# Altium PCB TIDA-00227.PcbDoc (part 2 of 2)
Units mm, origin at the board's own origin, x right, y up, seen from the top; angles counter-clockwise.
Board outline 100 x 100 mm, 2 copper layers (Top Layer, Bottom Layer), stack 1.575 mm thick; 148 components, 67 nets, 312 pads, 76 vias.
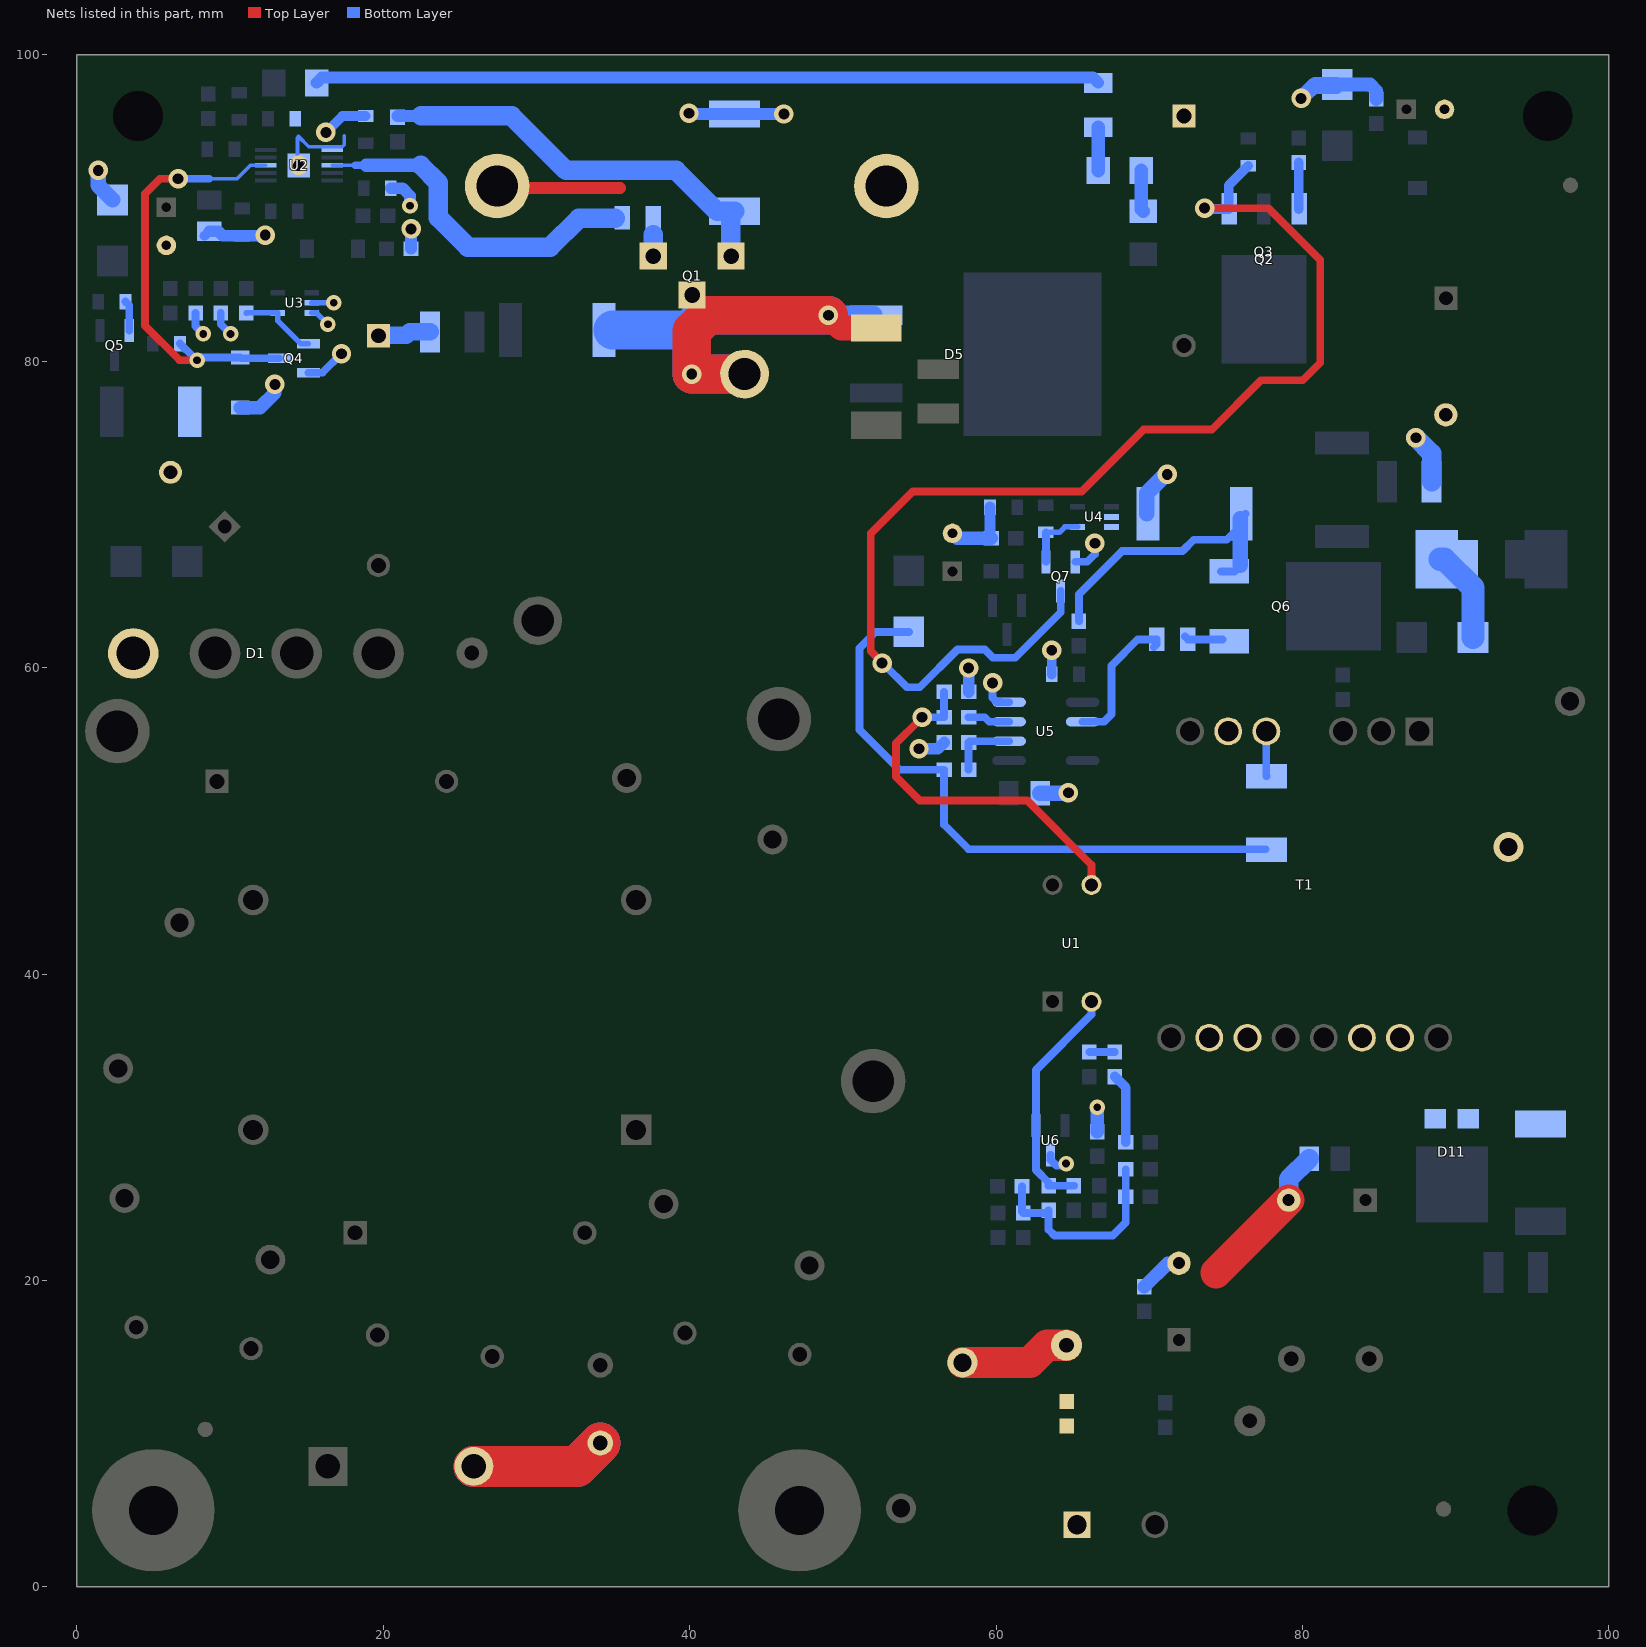
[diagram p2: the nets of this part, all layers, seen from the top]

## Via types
v1: diameter 1.27, hole 0.711, Top Layer to Bottom Layer, tented both sides, 65 vias
v2: diameter 1.016, hole 0.508, Top Layer to Bottom Layer, tented both sides, 8 vias
v3: diameter 2, hole 1, Top Layer to Bottom Layer, tented both sides, 3 vias

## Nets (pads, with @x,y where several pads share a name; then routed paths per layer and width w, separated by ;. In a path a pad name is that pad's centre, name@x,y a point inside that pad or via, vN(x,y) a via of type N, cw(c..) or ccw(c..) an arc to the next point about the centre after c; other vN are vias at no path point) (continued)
NetD5_3: D5.3 L1.2 Q1.2 R1.1 R19.2 | length 43
  Top Layer w1.651: v1(49.047,83.007) 49.886,82.169 R1.1@52.172,82.169
  Top Layer w2.54: L1.2@43.579,79.163 v1(40.132,79.163) 40.132,81.966 41.173,83.007 v1(49.047,83.007)
  Bottom Layer w1.245: v1(49.047,83.007) D5.3@51.967,83.007
  Bottom Layer w2.54: R19.2@34.976,82.042 39.929,82.042 40.132,82.245 ; L1.2@43.579,79.163 v1(40.132,79.163) 40.132,82.245 ; v1(49.047,83.007) 40.894,83.007 40.132,82.245
NetD7_1: D7.1 D9.1 D14.1 | length 6.1
  Bottom Layer w1.524: D7.1@88.989,67.081 89.256,67.081 91.129,65.208 D9.1@91.129,61.976
NetD8_2: D8.2 R32.1 R33.2 | length 40.8
  Bottom Layer w0.508: D8.2@54.305,62.338 52.153,62.338 51.079,61.265 51.079,55.956 53.696,53.34 R33.2@56.604,53.34 56.604,49.746 58.204,48.146 R32.1@77.597,48.146
NetD11_1: D11.1 D11.2 R36.1 T1.12 T1.13
NetD12_1: D12.1 Q4.3 R21.2 U2.3 | length 28.3
  Top Layer w0.508: v1(6.604,91.913) 5.426,91.913 4.445,90.932 4.445,82.321 6.706,80.061 v2(7.849,80.061)
  Bottom Layer w0.254: 8.636,91.913 10.455,91.913 11.339,92.796 U2.3@12.331,92.796
  Bottom Layer w0.508: v1(6.604,91.913) 8.636,91.913 ; R21.2@6.731,81.153 v2@7.62,80.264 ; v2(7.849,80.061) 8.038,80.25 D12.1@10.668,80.25 10.721,80.198 Q4.3@13.213,80.198
NetF1_1: F1.1 J1.2 | length 17.8
  Top Layer w2.667: J1.2@25.908,7.874 32.639,7.874 F1.1@34.163,9.398
  Bottom Layer w2.667: J1.2@25.908,7.874 32.639,7.874 F1.1@34.163,9.398
NetQ1_1: Q1.1 R14.2 | length 1.4
  Bottom Layer w1.27: Q1.1@37.617,86.868 37.617,88.265
NetQ1_3: Q1.3 R5.1 R6.2 | length 27.6
  Bottom Layer w0.762: R6.2@20.93,96.012 22.479,96.012
  Bottom Layer w0.889: R5.1@42.672,89.535 R5.1@42.926,89.789
  Bottom Layer w1.27: 22.479,96.012 28.372,96.012 31.928,92.456 39.116,92.456 41.783,89.789 R5.1@42.926,89.789 ; Q1.3@42.672,86.868 R5.1@42.672,89.535
NetQ2_1: Q2.1 Q3.1 Q7.3 R9.1 | length 79.5
  Top Layer w0.508: v1(52.553,60.3) 52.603,60.3 51.816,61.087 51.816,68.758 54.559,71.501 65.583,71.501 69.621,75.54 74.066,75.54 77.292,78.765 80.01,78.765 81.153,79.908 81.153,86.614 77.775,89.992 v1(73.609,89.992)
  Bottom Layer w0.508: v1(52.553,60.3) 52.603,60.3 54.178,58.725 55.016,58.725 57.48,61.189 59.258,61.189 59.792,60.655 61.239,60.655 64.211,63.627 Q7.3@64.211,65.014
  Bottom Layer w0.635: v1(73.609,89.992) 73.657,89.945 75.185,89.945 75.185,91.492 R9.1@76.454,92.761
NetQ2_3: Q2.3 Q3.3 R8.2 | length 3
  Bottom Layer w0.635: Q3.3@79.755,89.945 R8.2@79.756,92.977 R8.2@79.756,92.977
NetQ4_1: Q4.1 R16.2 U3.4 | length 5.2
  Bottom Layer w0.356: R16.2@11.049,83.147 11.059,83.157 U3.4@13.117,83.157 13.117,82.641 14.61,81.148 Q4.1@15.113,81.148
NetQ5_2: Q5.2 R20.1 | length 2
  Bottom Layer w0.508: R20.1@3.175,83.896 3.414,83.657 Q5.2@3.414,82.001
NetQ6_1: Q6.1 R28.2 | length 2.5
  Bottom Layer w0.508: R28.2@72.324,62.042 R28.2@72.517,61.849 74.33,61.849 Q6.1@74.778,61.849
NetQ6_3: Q6.3 R23.1 R27.2 | length 19.6
  Bottom Layer w0.508: R27.2@65.405,63.03 65.405,64.795 68.224,67.615 72.161,67.615 72.896,68.349 75.055,68.349 75.946,69.24 R23.1@75.946,69.721 ; Q6.3@74.682,66.288 Q6.3@75.213,66.288 75.559,66.288 Q6.3@75.946,66.675 ; R23.1@75.997,69.772 R23.1@75.946,69.721 ; R23.1@76.278,70.053 R23.1@75.946,69.721
  Bottom Layer w1.016: Q6.3@75.946,66.675 R23.1@75.946,69.721
NetQ7_1: Q7.1 R24.2 U4.4 | length 4.1
  Bottom Layer w0.356: R24.2@63.246,68.834 64.135,68.834 64.488,69.187 U4.4@65.314,69.187
  Bottom Layer w0.508: R24.2@63.246,68.834 63.246,66.929 Q7.1@63.261,66.914
NetR2_1: R2.1 R3.1 | length 51.3
  Bottom Layer w0.762: R3.1@15.646,98.171 16.002,98.527 66.322,98.527 R2.1@66.675,98.173
NetR2_2: R2.2 R10.2 | length 2.8
  Bottom Layer w0.889: R10.2@66.675,92.456 R2.2@66.675,95.273
NetR10_1: R10.1 R11.2 | length 2.7
  Bottom Layer w0.889: R10.1@69.469,92.456 69.469,89.916 R11.2@69.596,89.789
NetR14_1: R14.1 U2.8 | length 23.6
  Bottom Layer w0.254: U2.8@16.675,92.796 18.186,92.796
  Bottom Layer w0.508: 18.186,92.796 18.887,92.796
  Bottom Layer w0.889: 18.887,92.796 22.443,92.796 ; 22.215,92.796 22.817,92.194
  Bottom Layer w1.27: 22.443,92.796 23.597,91.643 23.597,89.383 25.527,87.452 30.886,87.452 32.766,89.332 R14.1@35.154,89.332
NetR28_1: R28.1 U5.6 | length 9.5
  Bottom Layer w0.508: U5.6@65.646,56.475 67.041,56.475 67.526,56.96 67.526,60.135 69.24,61.849 R28.1@70.485,61.849 70.485,61.544 R28.1@70.282,61.341
NetR29_2: R29.2 R30.1 U1.3 | length 24
  Top Layer w0.508: v1@55.169,56.54 54.94,56.54 53.467,55.067 53.467,52.883 55.016,51.333 62.027,51.333 66.218,47.142 U1.3@66.218,45.822
  Bottom Layer w0.508: v1(55.169,56.769) R30.1@56.604,56.769 R29.2@56.604,58.42
NetR30_2: R30.2 U5.3 | length 2.8
  Bottom Layer w0.508: R30.2@58.204,56.769 59.258,56.769 59.552,56.475 U5.3@60.846,56.475
NetR31_2: R31.2 R33.1 U5.2 | length 4.5
  Bottom Layer w0.508: R33.1@58.204,53.34 R31.2@58.204,55.118 58.291,55.205 U5.2@60.846,55.205
NetR32_2: R32.2 T1.4 | length 2.9
  Bottom Layer w0.508: T1.4@77.637,55.847 77.637,52.931 R32.2@77.648,52.921
NetR34_1: R34.1 R35.2 | length 1.7
  Bottom Layer w0.508: R35.2@66.091,34.912 R34.1@67.742,34.912
NetR34_2: R34.2 R38.1 | length 4.6
  Bottom Layer w0.635: R34.2@67.742,33.312 68.466,32.588 R38.1@68.466,29.032
NetR39_1: R39.1 R41.2 R42.2 R43.1 R44.1 | length 13.8
  Bottom Layer w0.508: R42.2@61.684,26.149 61.684,24.498 R44.1@61.773,24.409 63.246,24.409 R41.2@63.424,24.587 63.424,23.317 63.805,22.936 67.615,22.936 68.466,23.787 R43.1@68.466,25.476 R39.1@68.466,27.254
NetR40_1: R40.1 R41.1 U1.2 U6.1 | length 15.5
  Bottom Layer w0.508: R40.1@65.075,26.187 R41.1@63.424,26.187 63.424,26.391 62.601,27.214 U6.1@62.601,30.109 62.601,33.746 66.218,37.363 U1.2@66.218,38.202
PGND: C1.2 C2.1 C3.2 C4.1 C6.2 C7.2 C18.2 C20.1 C22.1 C23.2 C24.1 C25.2 C26.2 C27.1 C28.2 C29.2 C30.1 C31.1 C37.2 D1.4 D2.2 D4.2 D12.2 HT1.1 HT1.2 Q4.2 Q7.2 R5.2 R7.2 R15.1 R17.2 R23.2 R25.2 R29.1 R31.1 T1.5 U2.6 U2.11 U3.2 U3.3 U4.2 U4.3 U5.4 | length 78.6
  Top Layer w0.762: HT1.2@27.432,90.83 27.432,91.313 35.458,91.313
  Bottom Layer w0.254: v1(14.478,92.786) 14.402,92.862 14.402,94.59 14.478,94.666 15.138,94.005 17.323,94.005 17.45,94.132 17.45,94.717
  Bottom Layer w0.356: U3.3@15.326,83.157 15.649,83.157 v2(16.383,82.423) ; U3.2@15.326,83.817 16.761,83.817 v2(16.764,83.82)
  Bottom Layer w0.508: R17.2@7.747,83.147 7.747,82.296 v2(8.255,81.788) ; C25.2@9.398,83.147 9.398,82.423 v2(10.033,81.788) ; Q4.2@15.113,79.248 16.027,79.248 v1(17.272,80.493) ; v1(59.766,59.004) 59.766,58.039 60.046,57.76 60.35,57.76 60.365,57.745 U5.4@60.846,57.745 ; Q7.2@65.161,66.914 65.949,66.914 66.446,67.412 v1(66.446,68.123)
  Bottom Layer w0.635: C23.2@8.331,88.189 C23.2@8.56,88.417 ; v1(16.256,94.945) 17.323,96.012 C20.1@18.847,96.012 ; C30.1@63.627,59.563 v1(63.627,61.138) ; 80.518,97.765 D2.2@82.271,97.765
  Bottom Layer w0.737: R25.2@59.601,70.485 59.601,68.542 C29.2@59.69,68.453
  Bottom Layer w0.762: C23.2@8.636,88.494 9.22,88.494 9.525,88.189 C24.1@10.795,88.189 12.243,88.189 v1(12.294,88.24) ; C22.1@20.498,91.288 21.26,91.288 21.742,90.805 v2(21.742,90.145) ; R15.1@21.806,87.351 21.806,88.633 v1(21.819,88.646) ; v1@39.954,96.139 R5.2@42.926,96.139 v1(46.152,96.139) ; v1(54.966,54.712) 56.198,54.712 R31.1@56.604,55.118 ; R29.1@58.204,58.42 v1(58.204,59.982)
  Bottom Layer w0.889: D12.2@10.668,76.976 11.952,76.976 12.929,77.953 v1(12.929,78.486) ; C7.2@57.15,68.77 57.468,68.453 C29.2@59.69,68.453 ; D2.2@82.271,98.063 84.411,98.063 84.811,97.663 C18.2@84.811,97.117
  Bottom Layer w1.016: v1(1.397,92.456) 1.397,91.478 D4.2@2.337,90.538 ; C31.1@62.865,51.816 64.745,51.816 v1(64.719,51.841) ; R23.2@69.823,70.053 69.823,70.409 69.832,70.399 69.832,71.382 v1@71.171,72.72 ; v1(79.908,97.155) 80.518,97.765 80.816,98.063 D2.2@82.271,98.063
  Bottom Layer w1.143: C4.1@20.066,81.686 21.488,81.686 21.717,81.915 C26.2@23.061,81.915
  Bottom Layer w1.27: v1(87.401,75.006) 88.42,73.988 C28.2@88.42,72.136
  other v1: 71.171,72.619 39.954,96.19
PWR_GND: B1.2 J2.1
PWRGND: B1.1 C8.2 C12.2 C16.2 C17.2 C32.2 C36.2 R37.1 T1.8 T1.9 TP3.1 U6.3 | length 23.3
  Top Layer w2.032: C17.2@57.81,14.643 62.192,14.643 63.322,15.773 TP3.1@64.592,15.773 ; 74.358,20.511 C12.2@79.096,25.248
  Bottom Layer w0.508: U6.3@63.551,28.209 63.551,27.889 63.932,27.508 64.44,27.508 v2(64.567,27.635)
  Bottom Layer w0.889: R37.1@66.599,29.705 v2(66.599,31.318) ; C36.2@69.672,19.596 71.209,21.133 C16.2@71.933,21.133
  Bottom Layer w1.27: C12.2@79.096,25.248 79.096,26.619 C32.2@80.442,27.965
pads on no net: D5.1 D10.2 FID1.1 FID2.1 FID3.1 FID4.1 FID5.1 FID6.1 H1.1 H2.1 H3.1 H4.1 H5.1 H8.1 LBL1.0 Q3.2 T1.2 T1.6 T1.7 T1.10 T1.11 T1.14 U3.1 U4.1

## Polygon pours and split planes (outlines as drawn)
EARTH on Bottom Layer "Bottom Layer-No Net" (solid, pour order 50): 1.905,3.81 3.683,2.007 4.699,2.007 5.232,2.54 5.207,3.937 5.207,26.543 4.318,27.432 4.318,31.877 3.81,32.385 3.81,34.544 3.429,34.925 2.032,34.925 1.651,34.544 1.651,32.512 1.905,32.258
EARTH on Bottom Layer "Bottom Layer-No Net" (solid, remove dead copper, pour order 54): 44.323,46.863 45.847,45.339 45.847,28.321 46.482,27.686 46.482,7.62 45.466,6.604 45.466,3.556 46.482,2.54 48.133,2.54 49.784,4.191 49.784,28.448 49.149,29.083 49.149,44.831 46.482,47.498 46.482,49.53 46.101,49.911 44.45,49.911 44.323,49.784
NetC13_1 on Bottom Layer "Bottom Layer-No Net" (solid, remove dead copper, pour order 41): 16.256,24.384 16.256,20.066 20.447,20.066 20.828,20.447 20.828,23.749 19.939,24.638 16.51,24.638
PGND on Bottom Layer "Top Layer-No Net 1" (hatched 90Degree grid 0.127 track 0.254, remove dead copper, pour order 43): 5.588,72.136 5.334,72.39 5.334,73.152 6.477,74.295 6.477,78.486 6.731,78.74 8.763,78.74 9.779,77.724 12.446,77.724 12.446,76.962 12.192,76.708 10.668,76.708 7.239,73.279 7.239,72.39 6.985,72.136
NetC4_2 on Bottom Layer "Bottom Layer-No Net" (solid, pour order 42): 18.034,67.564 17.399,68.199 9.525,68.199 9.525,70.358 10.541,71.374 19.05,71.374 21.361,69.063 21.361,60.198 20.396,59.233 18.974,59.233 18.034,60.173
NetD5_3 on Bottom Layer "Bottom Layer-No Net" (solid, pour order 65): 40.97,84.785 39.802,84.785 38.1,83.083 38.1,81.153 39.611,79.642 42.062,82.093 42.062,83.693
PWRGND on Bottom Layer "Bottom Layer-No Net" (solid, pour order 63): 79.477,28.778 78.054,27.356 78.054,24.587 78.359,24.282 79.629,24.282 79.959,24.613 79.959,26.391 80.67,27.102 81.077,27.102 81.077,28.727 81.026,28.778
PWRGND on Bottom Layer "Bottom Layer-No Net" (solid, pour order 62): 70.028,21.946 68.859,20.777 68.859,19.329 69.088,19.101 70.282,19.101 70.282,19.736 70.815,20.269 72.238,20.269 72.72,20.752 72.72,21.539 72.314,21.946
NetB3_1 on Bottom Layer "Bottom Layer-No Net" (solid, pour order 59): 70.206,11.608 69.164,12.649 69.164,18.491 70.231,18.491 70.688,18.034 70.688,17.17 70.968,16.891 78.613,16.891 80.188,15.316 80.188,12.243 77.699,9.754 75.26,9.754 73.406,11.608
15V on Bottom Layer "Bottom Layer-No Net" (solid, pour order 60): 71.298,10.77 70.333,10.77 70.231,10.668 69.469,9.906 69.469,3.632 69.952,3.15 71.603,3.15 72.847,4.394 72.847,9.5 71.679,10.668 71.577,10.77 71.222,10.77
NetC35_1 on Bottom Layer "Bottom Layer-No Net" (solid, pour order 57): 96.774,24.765 94.183,24.765 93.929,24.511 93.904,24.486 93.904,23.266 93.904,23.012 94.666,22.25 94.717,22.2 94.717,21.082 94.717,19.253 94.767,19.202 95.885,19.202 96.444,19.202 96.977,19.736 97.206,19.964 97.206,23.139 97.206,24.765 97.079,24.765
NetC12_1 on Bottom Layer "Bottom Layer-No Net" (solid, pour order 56): 85.065,28.245 84.074,29.235 82.296,29.235 81.864,28.804 81.864,27.153 83.312,25.705 83.312,14.529 83.998,13.843 86.335,13.843 90.881,18.39 92.735,18.39 93.193,18.847 93.193,21.895 92.075,23.012 92.075,27.254 91.084,28.245
NetD11_1 on Bottom Layer "Bottom Layer-No Net" (solid, pour order 55): 83.693,36.805 86.741,36.805 87.147,36.398 87.274,36.271 87.274,35.458 87.274,33.477 88.367,32.385 96.799,32.385 97.765,31.42 97.765,29.743 97.231,29.21 95.199,29.21 93.65,29.21 93.04,29.82 92.989,29.87 90.907,29.87 86.538,29.87 83.795,32.614 82.956,33.452 82.956,36.068 82.956,36.322 83.185,36.551 83.439,36.805 83.464,36.805
NetB2_2 on Bottom Layer "Bottom Layer-No Net" (solid, pour order 45): 82.169,58.395 81.712,57.937 81.712,55.347 82.169,54.889 83.083,54.889 83.566,55.372 83.566,57.912 83.083,58.395
PGND on Bottom Layer "Bottom Layer-No Net" (solid, pour order 46): 67.056,70.028 68.072,70.028 68.097,70.002 68.148,69.952 68.148,69.088 68.148,68.859 66.802,67.513 65.684,66.396 65.151,66.396 65.151,67.742 66.091,68.682 66.192,68.783 66.751,68.783 66.802,68.783 67.005,68.986 67.031,69.012 67.031,69.723 67.031,70.028
NetF1_1 on Bottom Layer "Bottom Layer-No Net" (solid, pour order 52): 24.778,7.442 ccw(c25.514,7.442) 24.993,6.922 ccw(c25.945,7.873) 25.945,6.528 27.877,6.528 30.848,6.528 30.848,8.484 30.848,9.017 26.352,9.017 24.778,9.017
NetD5_3 on Bottom Layer "Bottom Layer-No Net" (solid, pour order 66): 48.158,84.277 53.873,84.277 53.873,81.737 48.158,81.737
NetB2_1 on Bottom Layer "Bottom Layer-No Net" (solid, pour order 44): 79.017,66.622 85.469,66.622 85.469,61.44 83.056,59.027 82.217,59.027 79.017,62.228
NetB2_1 on Bottom Layer "Bottom Layer-No Net" (solid, pour order 69): 80.797,69.291 78.918,67.412 78.918,61.112 86.284,61.112 86.284,67.818 84.811,69.291
NetC2_2 on Bottom Layer "Bottom Layer-No Net" (solid, pour order 70): 90.17,57.125 87.071,57.125 86.716,56.769 86.716,54.966 87.097,54.585 90.17,54.585
NetC2_2 on Bottom Layer "Bottom Layer-No Net" (solid, pour order 72): 57.887,86.639 58.699,87.452 65.583,87.452 69.545,83.49 69.545,77.699 66.98,75.133 57.887,75.133
PGND on Bottom Layer "Bottom Layer-No Net" (solid, pour order 47): 14.351,96.342 14.351,95.809 13.691,95.148 13.691,90.373 13.843,90.221 14.3,90.221 15.392,91.313 15.392,93.243 16.231,94.082 17.475,94.082 17.577,94.183 17.577,95.047 17.297,95.326 17.297,95.707 16.993,96.012 16.612,96.012 16.281,96.342
NetQ1_3 on Bottom Layer "Bottom Layer-No Net" (solid, pour order 76): 41.3,90.678 41.046,90.424 41.046,86.741 41.808,85.979 43.764,85.979 44.602,86.817 44.602,90.678
EARTH on Top Layer "Bottom Layer-No Net" (solid, pour order 49): 1.905,3.81 3.683,2.007 4.699,2.007 5.232,2.54 5.207,3.937 5.207,26.543 4.318,27.432 4.318,31.877 3.81,32.385 3.81,34.544 3.429,34.925 2.032,34.925 1.651,34.544 1.651,32.512 1.905,32.258
EARTH on Top Layer "Bottom Layer-No Net" (solid, remove dead copper, pour order 53): 44.323,46.863 45.847,45.339 45.847,28.321 46.482,27.686 46.482,7.62 45.466,6.604 45.466,3.556 46.482,2.54 48.133,2.54 49.784,4.191 49.784,28.448 49.149,29.083 49.149,44.831 46.482,47.498 46.482,49.53 46.101,49.911 44.45,49.911 44.323,49.784
NetC13_1 on Top Layer "Bottom Layer-No Net" (solid, remove dead copper, pour order 40): 16.256,24.384 16.256,20.066 20.447,20.066 20.828,20.447 20.828,23.749 19.939,24.638 16.51,24.638
NetD5_3 on Top Layer "Bottom Layer-No Net" (solid, remove dead copper, pour order 74): 51.181,83.439 53.873,83.439 53.873,81.229 51.181,81.229
PGND on Top Layer "Bottom Layer-No Net" (solid, remove dead copper, pour order 73): 0.889,90.424 0.864,75.54 1.702,74.701 1.702,60.528 2.997,59.233 4.369,59.233 5.486,60.35 5.486,70.739 11.252,76.505 11.938,76.505 15.062,79.629 25.222,79.629 35.128,89.535 45.237,89.535 46.304,88.468 55.575,88.468 58.547,91.44 83.744,91.44 84.887,90.297 90.475,90.297 92.862,87.909 92.862,81.534 88.08,76.751 78.07,76.751 74.844,73.525 70.706,73.525 66.726,69.545 55.448,69.545 53.779,67.876 53.779,61.535 53.922,61.392 54.508,61.392 56.032,59.868 56.032,56.365 54.364,54.696 54.364,53.254 55.319,52.299 63.297,52.299 64.414,51.181 65.024,51.181 65.38,51.537 65.38,54.801 68.939,58.347 69.317,58.725 70.968,58.725 71.399,59.157 71.399,71.628 73.203,71.628 73.203,58.979 74.244,57.937 74.244,55.423 74.752,54.915 75.54,54.915 76.085,55.46 76.085,59.094 75.336,59.842 75.336,67.996 80.188,72.847 88.57,72.847 89.433,73.711 89.433,74.955 91.592,77.114 96.241,77.114 97.155,78.029 97.155,89.129 92.151,94.132 92.151,95.682 90.119,97.714 85.448,97.714 85.404,97.757 55.13,97.757 50.921,93.548 47.625,93.548 47.625,96.52 46.482,97.663 9.779,97.663 8.763,96.647 8.763,90.424 6.731,88.392 5.461,88.392 5.207,88.138 5.207,87.122 5.334,86.995 22.098,86.995 23.52,88.417 23.52,94.285 24.587,95.352 45.263,95.352 45.263,93.548 26.391,93.548 25.324,92.481 25.324,86.868 22.885,84.43 7.493,84.43 6.985,83.922 6.985,81.864 7.595,81.255 8.611,81.255 9.093,80.772 9.093,79.477 8.458,78.842 6.096,78.842 3.429,81.509 3.429,91.694 2.54,92.583 1.143,92.583 0.889,92.329
NetC4_2 on Top Layer "Bottom Layer-No Net" (solid, pour order 39): 18.034,67.564 17.653,67.945 9.398,67.945 9.144,68.199 9.144,69.977 10.414,71.247 19.177,71.247 21.361,69.063 21.361,60.198 20.396,59.233 18.974,59.233 18.034,60.173
PWRGND on Top Layer "Bottom Layer-No Net" (solid, pour order 58): 73,33.02 77.445,28.575 77.445,24.613 77.775,24.282 79.146,24.282 80.112,25.248 80.112,31.826 77.318,34.62 77.318,37.465 76.759,38.024 73.406,38.024 73,37.617
PWR_GND on Top Layer "Bottom Layer-No Net" (solid, pour order 61): 64.846,10.922 63.729,10.922 62.814,10.008 62.814,4.013 63.576,3.251 63.703,3.124 64.948,3.124 66.065,3.124 66.142,3.2 66.142,9.982 65.227,10.897 65.202,10.922 65.126,10.922
PWRGND on Top Layer "Bottom Layer-No Net" (solid, pour order 48): 73,36.271 73,38.227 75.438,40.665 89.23,40.665 92.304,43.739 92.304,48.743 92.913,49.352 94.056,49.352 94.539,48.87 94.539,42.621 90.043,38.125 78.283,38.125 77.292,37.135 77.318,37.109 77.318,35.966
NetF1_1 on Top Layer "Bottom Layer-No Net" (solid, pour order 51): 24.778,7.442 ccw(c25.514,7.442) 24.993,6.922 ccw(c25.945,7.873) 25.945,6.528 27.877,6.528 30.848,6.528 30.848,8.484 30.848,9.017 26.352,9.017 24.778,9.017
NetC12_1 on Top Layer "Bottom Layer-No Net" (solid, pour order 67): 92.405,32.106 87.909,32.106 86.69,30.886 86.462,30.658 86.462,27.534 86.462,27.381 85.115,26.035 85.09,26.01 84.506,26.01 83.337,26.01 83.337,24.486 85.014,24.486 85.293,24.206 85.293,17.831 85.293,16.967 84.176,15.85 83.591,15.265 83.591,14.554 83.617,14.554 84.201,13.97 86.258,13.97 86.665,14.376 94.539,22.25 94.539,24.765 94.539,31.318 93.751,32.106 93.497,32.106
NetB2_1 on Top Layer "Bottom Layer-No Net" (solid, pour order 68): 80.112,66.98 81.864,68.732 87.681,68.732 88.875,67.539 88.875,62.205 87.757,61.087 80.747,61.087 80.112,61.722
NetC2_2 on Top Layer "Bottom Layer-No Net" (solid, pour order 71): 59.182,78.511 60.223,77.47 66.954,77.47 69.52,80.035 69.52,86.258 68.605,87.173 60.477,87.173 59.182,85.877
NetD5_3 on Top Layer "Bottom Layer-No Net" (solid, pour order 75): 38.862,81.102 38.862,83.845 39.878,84.861 40.894,84.861 41.478,84.277 42.113,84.277 42.113,81.737 41.707,81.737 41.402,81.432 41.402,81.102
PWRGND on Top Layer "Bottom Layer-No Net" (solid, pour order 64): 62.611,31.877 59.284,28.55 59.284,14.402 61.874,11.811 65.151,11.811 66.269,12.929 66.269,17.323 68.301,19.355 68.326,19.329 74.625,19.329 78.842,23.546 78.842,25.883 78.334,25.883 76.632,24.181 72.836,24.181 69.723,27.294 69.723,30.658 68.504,31.877

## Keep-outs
Keep-Out Layer:
  lines w0.2: 12.319,2.921 12.319,5.461 28.575,5.461 28.575,2.921 12.319,2.921
  text ".Layer_Name" at 14.453,-22.212 h1.52

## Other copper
Top Layer:
  text ".Layer_Name" at 14.453,-22.212 h1.52
Bottom Layer:
  rectangle net NetC19_2: 12.04,93.878 12.903,95.072
  text ".Layer_Name" at 14.453,-22.212 h1.52

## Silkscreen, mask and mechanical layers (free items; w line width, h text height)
Top Overlay:
  circle w0.152: c5.842,88.824 r3.531
  circle w0.152: c61.602,38.152 r0.304
  circle w0.152: c81.699,6.744 r1.6
  lines w0.152: 80.645,7.823 82.779,5.689 ; 50.14,74.549 50.14,83.439 54.204,83.439 54.204,74.549 50.14,74.549
  text "ISE3033" at 91.872,10.719 h1.52 r90
  text "REV : A1" at 97.333,10.719 h1.52 r90
  text "TIDA-00227" at 94.564,10.643 h1.52 r90
  text "PB" at 80.709,6.134 h1.27
  text ".layer_Name" at 14.435,-22.204 h1.52
Bottom Overlay:
  circle w0.152: c90.965,32.198 r0.282
  lines w0.152: 5.283,90.957 7.239,90.957 7.442,90.754 ; 9.957,90.856 9.957,91.542 ; 15.748,88.621 14.148,88.621 14.148,86.081 19.228,86.081 19.228,88.621 17.475,88.621 ; 17.958,90.399 21.26,90.399 21.26,92.177 17.958,92.177 17.958,90.424 ; 57.785,69.85 58.674,68.961 ; 58.42,65.227 58.42,65.557 58.776,65.913 58.928,65.913 ; 62.865,60.452 62.865,58.674 66.167,58.674 66.167,60.452 64.135,60.452 ; 71.005,26.756 71.338,26.756 71.61,26.484 ; 86.233,92.075 86.233,90.424 88.773,90.424 88.773,95.504 86.233,95.504 86.233,93.853 ; 0.572,85.141 0.572,91.961 3.746,91.961 3.746,85.141 3.708,85.141 0.572,85.141 ; 0.635,83.007 0.635,84.785 3.937,84.785 3.937,83.007 0.635,83.007 ; 1.143,74.676 1.143,78.715 8.509,78.715 8.509,74.676 1.143,74.676 ; 4.191,80.264 4.191,82.042 7.493,82.042 7.493,80.264 4.191,80.264 ; 7.696,94.996 7.696,98.298 9.474,98.298 9.474,94.996 7.696,94.996 ; 7.747,92.939 7.747,94.717 11.049,94.717 11.049,92.939 7.747,92.939 ; 9.703,94.996 9.703,98.298 11.481,98.298 11.481,94.996 9.703,94.996 ; 9.906,87.427 9.906,90.729 11.684,90.729 11.684,87.427 9.906,87.427 ; 11.709,94.945 11.709,96.723 15.011,96.723 15.011,94.945 11.709,94.945 ; 11.709,96.901 11.709,99.441 16.789,99.441 16.789,96.901 11.709,96.901 ; 11.887,88.9 11.887,90.678 15.189,90.678 15.189,88.9 11.887,88.9 ; 17.958,93.472 17.958,96.774 19.736,96.774 19.736,93.472 17.958,93.472 ; 34.696,88.214 34.696,90.5 38.506,90.5 38.506,88.214 34.696,88.214 ; 40.894,88.519 40.894,97.409 44.958,97.409 44.958,88.519 40.894,88.519 ; 58.839,69.596 58.839,71.374 62.141,71.374 62.141,69.596 58.839,69.596 ; 62.357,68.072 62.357,71.374 64.135,71.374 64.135,68.072 62.357,68.072 ; 65.532,91.186 65.532,93.726 70.612,93.726 70.612,91.186 65.532,91.186 ; 68.326,85.852 70.866,85.852 70.866,90.932 68.326,90.932 68.326,85.852 ; 69.596,60.706 69.596,62.992 73.406,62.992 73.406,60.706 69.596,60.706 ; 75.565,91.999 75.565,95.301 77.343,95.301 77.343,91.999 75.565,91.999 ; 93.497,22.606 93.497,31.496 97.561,31.496 97.561,22.606 93.497,22.606
  text ".Layer_Name" at 14.453,-22.212 h1.52
Top Paste:
  text ".Layer_Name" at 14.453,-22.212 h1.52
Bottom Paste:
  text ".Layer_Name" at 14.453,-22.212 h1.52
Top Solder:
  text ".Layer_Name" at 14.453,-22.212 h1.52
  text ".Layer_Name" at 14.453,-22.212 h1.52
Bottom Solder:
  text ".Layer_Name" at 14.453,-22.212 h1.52
Drill Guide:
  text ".Layer_Name" at 14.453,-22.212 h1.52
M1 Board Outline:
  the board outline again, w0.152
  text ".Layer_Name" at 14.224,-22.098 h1.52
M2 Board Dimensions:
  rectangle: -0.216,-7.658 2.959,-4.483
  rectangle: 2.959,-10.833 12.484,-7.658
  lines w0.178: -0.216,-7.658 25.184,-7.658 ; 2.959,-10.833 2.959,-4.483 ; 6.134,-10.833 6.134,-4.483 ; 12.484,-10.833 12.484,-4.483 ; 18.834,-10.833 18.834,-4.483 ; -0.216,-10.833 25.184,-10.833 25.184,-4.483 -0.216,-4.483 -0.216,-10.833
  lines w0.254: -0.216,-12.484 -0.216,-11.976 ; 1.308,-12.738 -0.216,-12.23 ; 1.308,-11.722 -0.216,-12.23 ; 5.984,-12.23 -0.216,-12.23 ; 18.985,-12.23 25.184,-12.23 ; 23.66,-12.738 25.184,-12.23 ; 23.66,-11.722 25.184,-12.23 ; 25.184,-12.484 25.184,-11.976
  text "25.4 (mm)" at 6.238,-13.144 h1.52
M3 3D STEP Top:
  text ".Layer_Name" at 14.453,-22.212 h1.52
M4 3D STEP Bottom:
  text ".Layer_Name" at 14.453,-22.212 h1.52
M5 Assembly Top:
  lines w0.254: -7.62,-24.033 160.02,-24.033 ; -7.62,-18.868 160.071,-18.868 ; -7.62,-13.703 -7.62,-29.197 94.107,-29.197 160.071,-29.197 160.071,-13.703 -7.607,-13.703 -7.607,-29.197 32.41,-29.197 ; 54.991,-29.197 54.991,-13.703 ; 87.173,-18.868 87.173,-13.703 ; 108.509,-18.868 108.509,-13.703 ; 124.308,-29.362 124.308,-24.21
  text "ISE3033" at 91.872,10.719 h1.52 r90
  text "REV : A1" at 97.333,10.719 h1.52 r90
  text "TIDA-00227" at 94.564,10.643 h1.52 r90
  text "COMPONENTS MARKED 'DNP' SHOULD NOT BE POPULATED." at 29.096,-8.496 h1.52
  text "ASSEMBLY VARIANT:" at 29.083,-11.43 h1.52
  text ".VariantName" at 55.397,-11.43 h1.52
  text "PCB VIEWED FROM TOP SIDE" at -6.007,-17.06 h1.52
  text "BOARD #:" at 56.896,-17.06 h1.52
  text ".PRJ_Number" at 70.752,-17.06 h1.52
  text "REV:" at 92.202,-17.06 h1.52
  text ".PCB_Rev" at 99.606,-17.06 h1.52
  text "SVN REV:" at 113.487,-17.06 h1.52
  text ".VersionControl_RevNumber" at 126.34,-17.06 h1.52
  text ".Layer_Name" at 14.453,-22.212 h1.52
  text "LAYER NAME =" at -6.007,-22.217 h1.52
  text "TIDA-00227" at 61.138,-22.377 h1.52
  text "PLOT NAME =" at -6.007,-27.441 h1.52
  text ".plot_File_Name" at 14.453,-27.441 h1.52
  text "GENERATED    :" at 56.947,-27.441 h1.52
  text ".Print_Date" at 79.032,-27.441 h1.52
  text ".Print_Time" at 97.549,-27.441 h1.52
  text "TEXAS INSTRUMENTS" at 129.667,-27.441 h1.52
M6 Assembly Bottom:
  lines w0.254: -7.601,-18.873 160.09,-18.873 ; -7.55,-24.038 160.09,-24.038 ; 18.536,-29.215 18.536,-24.063 ; 43.961,-18.873 43.961,-13.709 ; 56.623,-18.763 56.623,-13.599 ; 97.479,-29.203 97.479,-13.709 ; 120.059,-29.203 160.077,-29.203 160.077,-13.709 -7.601,-13.709 -7.601,-29.203 58.363,-29.203 160.09,-29.203 160.09,-13.709
  text "COMPONENTS MARKED 'DNP' SHOULD NOT BE POPULATED." at 154.819,-8.476 h1.52
  text ".VariantName" at 128.302,-11.423 h1.52
  text "ASSEMBLY VARIANT:" at 154.692,-11.423 h1.52
  text ".VersionControl_RevNumber" at 26.13,-17.066 h1.52
  text "SVN REV:" at 38.983,-17.066 h1.52
  text "BOARD #:" at 95.574,-17.066 h1.52
  text "PCB VIEWED FROM BOTTOM SIDE" at 158.477,-17.066 h1.52
  text ".PRJ_Number" at 83.318,-17.188 h1.52
  text "A1" at 48.965,-17.251 h1.52
  text "REV:" at 55.682,-17.251 h1.52
  text "LAYER NAME =" at 157.537,-22.167 h1.52
  text ".layer_Name" at 137.598,-22.294 h1.52
  text "TIDA-00227" at 93.877,-22.557 h1.52
  text ".plot_File_Name" at 143.11,-27.399 h1.52
  text ".Print_Time" at 34.474,-27.425 h1.52
  text ".Print_Date" at 52.991,-27.425 h1.52
  text "GENERATED:" at 75.076,-27.425 h1.52
  text "PLOT NAME=" at 158.477,-27.446 h1.52
  text "TEXAS INSTRUMENTS" at 17.99,-27.526 h1.52
M7 LPKF Text Top:
  lines w0.254: -7.633,-18.881 160.058,-18.881 ; -7.582,-24.045 160.058,-24.045 ; 28.13,-29.375 28.13,-24.223 ; 43.929,-18.881 43.929,-13.716 ; 65.265,-18.881 65.265,-13.716 ; 97.447,-29.21 97.447,-13.716 ; 120.028,-29.21 160.045,-29.21 160.045,-13.716 -7.633,-13.716 -7.633,-29.21 58.331,-29.21 160.058,-29.21 160.058,-13.716
  text "COMPONENTS MARKED 'DNP' SHOULD NOT BE POPULATED." at 154.788,-8.484 h1.52
  text ".VariantName" at 128.27,-11.43 h1.52
  text "ASSEMBLY VARIANT:" at 154.661,-11.43 h1.52
  text ".VersionControl_RevNumber" at 26.098,-17.073 h1.52
  text "SVN REV:" at 38.951,-17.073 h1.52
  text ".PCB_Rev" at 52.832,-17.073 h1.52
  text "REV:" at 60.236,-17.073 h1.52
  text ".PRJ_Number" at 81.686,-17.073 h1.52
  text "BOARD #:" at 95.542,-17.073 h1.52
  text "Bottom Overlay" at 143.065,-22.119 h1.52
  text "TIDA-00127-PRPS" at 82.982,-22.25 h1.52
  text "TEXAS INSTRUMENTS" at 22.771,-27.453 h1.52
  text ".Print_Time" at 54.889,-27.453 h1.52
  text ".Print_Date" at 73.406,-27.453 h1.52
  text "GENERATED    :" at 95.491,-27.453 h1.52
  text "Bottom Overlay" at 137.986,-27.453 h1.52
  text "PLOT NAME =" at 158.445,-27.453 h1.52
M9 Title Sheet:
  drawing of 56 lines, arcs and shapes, not listed
  text "1" at 18.589,203.721 h1.78
  text "2" at 81.978,203.721 h1.78
  text "3" at 145.208,203.721 h1.78
  text "5" at 272.351,203.721 h1.78
  text "6" at 335.978,203.721 h1.78
  text "A" at -10.782,174.689 h1.78
  text "A" at 365.138,174.689 h1.78
  text "B" at -10.782,114.236 h1.78
  text "B" at 365.138,114.236 h1.78
  text "C" at -10.782,53.911 h1.78
  text "C" at 365.138,53.911 h1.78
  text "PROJECT TITLE:" at 287.922,6.642 h1.14
  text ".PRJ_Title" at 289.192,3.256 h2.54
  text "DESIGNED FOR:" at 287.922,-1.003 h1.14
  text ".PRJ_Customer" at 289.192,-4.559 h2.54
  text "D" at -10.782,-6.286 h1.78
  text "D" at 365.138,-6.286 h1.78
  text "FILE NAME:" at 287.922,-8.623 h1.14
  text "TIDA-00227" at 289.192,-11.671 h2.54
  text "Texas Instruments (TI) and/or its licensors do not warrant the accuracy or completeness of this specification" at 161.696,-15.782 h1.14
  text "ENGINEER:" at 287.922,-15.989 h1.14
  text "LAYOUT BY:" at 326.149,-15.989 h1.14
  text "or any information contained therein. TI and/or its licensors do not warrant that this design will meet" at 160.554,-18.644 h1.14
  text "Sunil D" at 289.192,-19.926 h2.54
  text ".PCB_Layout" at 327.431,-19.926 h1.78
  text "the specifications, will be suitable for your application or fit for any particular purpose, or will operate in" at 160.554,-21.505 h1.14
  text "ALTIUM DESIGNER VERSION:" at 326.149,-23.863 h1.14
  text "an implementation. TI and/or its licensors do not warrant that the design is production worthy. You should" at 160.554,-24.367 h1.14
  text "completely validate and test your design implementation to confirm the system functionality for your application." at 161.696,-27.229 h1.14
  text ".print_Scale" at 289.192,-27.25 h1.78
  text ".Application_BuildNumber" at 327.431,-27.25 h1.78
  text "1" at 18.589,-32.499 h1.78
  text "2" at 81.978,-32.499 h1.78
  text "3" at 145.208,-32.499 h1.78
  text "4" at 208.877,-32.499 h1.78
  text "5" at 272.351,-32.499 h1.78
  text "6" at 335.978,-32.499 h1.78
M10 Fab Notes:
  drawing of 220 lines, arcs and shapes, not listed
  text "DESIGN INFORMATION" at 314.275,172.568 h1.52
  text "(REFER ALSO ARRAY/PANEL PROFILING INFORMATION)" at 305.091,168.46 h1.52
  text "BOARD SIZE" at 287.667,168.351 h1.52
  text "100MM" at 297.866,165.202 h1.52
  text "100MM" at 316.408,165.202 h1.52
  text "X" at 312.254,165.105 h1.52
  text "Number of Layers :" at 297.903,160.096 h1.52
  text "2" at 325.711,159.842 h1.52
  text "MIN. TRACK WIDTH:" at 297.903,156.566 h1.52
  text "10" at 325.747,156.566 h1.52
  text "MIL" at 329.678,156.566 h1.52
  text "MIN. CLEARANCE:" at 297.903,153.213 h1.52
  text "8" at 325.747,153.213 h1.52
  text "MIL" at 329.678,153.213 h1.52
  text "MIN. VIA PAD SIZE:" at 297.903,149.86 h1.52
  text "40" at 324.986,149.86 h1.52
  text "MIL" at 329.678,149.86 h1.52
  text "0.05mm (2MIL)" at 315.556,146.261 h1.52
  text "MINIMUM ANNULAR RING" at 289.54,146.152 h1.52
  text "EXTERNAL" at 333.539,146.152 h1.52
  text "PER" at 294.62,143.154 h1.52
  text "IPC-D-275 CLASS 2 LEVEL C" at 300.208,143.154 h1.52
  text "MIL, HOLES" at 338.009,140.302 h1.52
  text "+/-" at 328.041,140.284 h1.52
  text "+/-" at 349.733,140.284 h1.52
  text "REGISTRATION TOLERANCES:" at 289.54,140.157 h1.52
  text "METAL" at 320.015,140.157 h1.52
  text "5" at 334.65,140.157 h1.52
  text "3" at 355.808,140.157 h1.52
  text "MIL" at 358.761,140.157 h1.52
  text "MATERIAL:" at 287.641,134.837 h1.52
  text "FR-4 High Tg" at 312.697,131.272 h1.52
  text "FR-408" at 298.335,131.055 h1.52
  text "X" at 308.799,131.055 h1.52
  text "OTHER" at 336.13,131.055 h1.52
  text "62 MIL (1.6mm) +/-10%" at 306.465,126.922 h1.52
  text "THICKNESS:" at 289.54,126.813 h1.52
  text "X" at 303.21,126.813 h1.52
  text "OTHER" at 339.102,126.813 h1.52
  text "TOLERANCE:" at 289.54,122.8 h1.52
  text "X" at 310.859,122.8 h1.52
  text "ANSI IPC-6012 TYPE 3 CLASS 2" at 315.607,122.8 h1.52
  text "OTHER +/-" at 315.607,118.837 h1.52
  text "BOW & TWIST:" at 289.54,114.85 h1.52
  text "X" at 310.859,114.85 h1.52
  text "ANSI IPC-6012 TYPE 3 CLASS 2" at 315.607,114.85 h1.52
  text "OTHER +/-" at 315.607,110.824 h1.52
  text "COPPER THICKNESS (FINISHED):" at 287.641,107.382 h1.52
  text "1.4MIL (1oz)" at 309.993,103.503 h1.52
  text "2MIL (1.4oz)" at 329.475,103.503 h1.52
  text "2.8MIL (2oz)" at 347.941,103.503 h1.52
  text "OUTER:" at 296.709,103.394 h1.52
  text "X" at 306.73,103.378 h1.52
  text "1.4MIL (1oz)" at 309.993,99.515 h1.52
  text "2.8MIL (2oz)" at 329.475,99.515 h1.52
  text "N/A" at 347.929,99.524 h1.52
  text "INNER SIGNAL:" at 289.366,99.406 h1.52
  text "DRILLING:" at 287.641,95.876 h1.52
  text "REFERENCE:" at 289.54,92.904 h1.52
  text "X" at 306.005,92.904 h1.52
  text "AS SHOWN" at 310.755,92.904 h1.52
  text "X" at 328.891,92.904 h1.52
  text "NC_DRILL FILES" at 332.371,92.904 h1.52
  text "PTH MIN COPPER THICKNESS:" at 289.54,88.891 h1.52
  text "X" at 323.836,88.891 h1.52
  text "1MIL" at 327.316,88.891 h1.52
  text "OTHER" at 339.94,88.891 h1.52
  text "BOARD FINISH:" at 287.641,84.852 h1.52
  text "SILKSCREEN:" at 291.584,81.855 h1.52
  text "X" at 315.683,81.855 h1.52
  text "TOP" at 318.883,81.855 h1.52
  text "X" at 328.637,81.855 h1.52
  text "BOTTOM" at 331.863,81.855 h1.52
  text "SILKSCREEN COLOR:" at 291.584,77.613 h1.52
  text "X" at 315.656,77.613 h1.52
  text "WHITE" at 318.883,77.613 h1.52
  text "OTHER" at 331.863,77.613 h1.52
  text "SOLDER RESIST COLOR:" at 291.584,73.295 h1.52
  text "X" at 306.005,69.252 h1.52
  text "GREEN" at 309.231,69.252 h1.52
  text "BLUE" at 324.243,69.252 h1.52
  text "OTHER" at 337.908,69.252 h1.52
  text "IMMERSION GOLD (ENIG)" at 314.591,64.463 h1.52
  text "ENEPIG" at 348.564,64.38 h1.52
  text "SURFACE FINISH:" at 287.641,64.354 h1.52
  text "X" at 309.842,64.354 h1.52
  text "IMM. TIN/SILVER OR EQUIV" at 296.012,60.367 h1.52
  text "OTHER" at 332.371,60.367 h1.52
  text "ARRAY/PANEL:" at 287.641,55.82 h1.52
  text "CUT AND TRIM PER MECH LAYER 1" at 314.591,55.711 h1.52
  text "N.C. ROUTE" at 314.591,51.858 h1.52
  text "X" at 331.837,51.858 h1.52
  text "V. SCORE" at 336.587,51.858 h1.52
  text "CERTIFICATION:" at 287.641,48.378 h1.52
  text "MATERIALS AND WORKMANSHIP FOR ALL PCBS" at 306.056,48.378 h1.52
  text "TO MEET OR EXCEED THE REQUIREMENTS OF:" at 306.056,45.889 h1.52
  text "X" at 296.569,42.421 h1.52
  text "ANSI IPC-A-600F CLASS ->" at 300.1,42.421 h1.52
  text "X" at 341.732,42.421 h1.52
  text "2" at 344.753,42.421 h1.52
  text "1" at 336.752,42.383 h1.52
  text "3" at 353.745,42.383 h1.52
  text "X" at 296.622,38.37 h1.52
  text "UL 94V-0" at 300.1,38.37 h1.52
  text "X" at 317.246,38.37 h1.52
  text "RoHS" at 320.725,38.37 h1.52
  text "OTHER" at 337.093,38.37 h1.52
  text "PER ORDER" at 347.178,38.37 h1.52
  text "ADDITIONAL REQUIREMENTS:" at 287.641,34.789 h1.52
  text "REQUIRED" at 351.624,32.156 h1.52
  text "VIA TENTING:" at 322.682,32.131 h1.52
  text "NONE" at 340.918,32.084 h1.52
  text "X" at 348.398,32.084 h1.52
  text "MICROSECTION:" at 289.54,31.868 h1.52
  text "YES" at 312.546,31.868 h1.52
  text "REQUIRED" at 334.428,27.902 h1.52
  text "BARE BOARD ELEC. TEST:" at 289.54,27.829 h1.52
  text "NONE" at 322.706,27.829 h1.52
  text "X" at 331.202,27.829 h1.52
  text "PER ORDER" at 349.465,27.829 h1.52
  text "MANUFACTURER'S UL:" at 289.54,23.841 h1.52
  text "RAIL" at 319.15,23.733 h1.52
  text "METAL" at 331.642,23.733 h1.52
  text "X" at 341.173,23.724 h1.52
  text "SILK" at 344.639,23.733 h1.52
M11 Gerber Information:
  lines w0.254: -7.62,-24.033 160.02,-24.033 ; -7.62,-18.868 160.071,-18.868 ; -7.62,-13.703 -7.62,-29.197 94.107,-29.197 160.071,-29.197 160.071,-13.703 -7.607,-13.703 -7.607,-29.197 32.41,-29.197 ; 54.991,-29.197 54.991,-13.703 ; 87.173,-18.868 87.173,-13.703 ; 108.509,-18.868 108.509,-13.703 ; 124.308,-29.362 124.308,-24.21
  text "BOARD #:" at 56.921,-17.043 h1.52
  text "ALL ARTWORK VIEWED FROM TOP SIDE" at -6.007,-17.06 h1.52
  text ".PRJ_Number" at 70.764,-17.069 h1.52
  text "REV:" at 92.202,-17.06 h1.52
  text "SVN REV:" at 113.487,-17.06 h1.52
  text ".VersionControl_RevNumber" at 126.34,-17.06 h1.52
  text "A1" at 99.619,-17.094 h1.52
  text "LAYER NAME =" at -6.007,-22.212 h1.52
  text "TIDA-00227" at 61.138,-22.25 h1.52
  text "PLOT NAME =" at -6.007,-27.441 h1.52
  text ".plot_File_Name" at 14.453,-27.441 h1.52
  text "GENERATED    :" at 56.947,-27.441 h1.52
  text ".Print_Date" at 79.032,-27.441 h1.52
  text ".Print_Time" at 97.549,-27.441 h1.52
  text "TEXAS INSTRUMENTS" at 129.667,-27.441 h1.52
M12 Stackup:
  lines w0.2: 287.909,192.928 360.934,192.928 ; 287.909,196.408 360.934,196.408 ; 286.385,176.995 ccw(c287.485,176.995) 287.485,175.895 361.358,175.895 ccw(c361.358,176.995) 362.458,176.995 362.458,200.195 ccw(c361.358,200.195) 361.358,201.295 287.485,201.295 ccw(c287.485,200.195) 286.385,200.195 286.385,176.995
  text "Layer Stack Up Detail for: TIDA-00227.PcbDoc" at 287.909,197.672 h1.6
  text "Layer" at 287.909,195.108 h0.8
  text "Gerber" at 313.745,195.108 h0.8
  text "Copper" at 329.117,195.108 h0.8
  text "Dielectric" at 345.796,195.108 h0.8
  text "Name" at 287.909,193.508 h0.8
  text "Document" at 313.745,193.508 h0.8
  text "Thickness" at 329.117,193.508 h0.8
  text "Material" at 345.796,193.508 h0.8
  text "Top Solder Mask" at 287.909,190.447 h1.1
  text "(.GTS)" at 313.745,190.447 h1.1
  text "Solder Resist" at 345.796,190.447 h1.1
  text "Top Layer" at 287.909,187.272 h1.1
  text "(.GTL)" at 313.745,187.272 h1.1
  text "0.0356mm" at 329.117,187.272 h1.1
  text "FR-4" at 345.796,185.685 h1.1
  text "Bottom Layer" at 287.909,184.097 h1.1
  text "(.GBL)" at 313.745,184.097 h1.1
  text "0.0356mm" at 329.117,184.097 h1.1
  text "Bottom Solder Mask" at 287.909,180.922 h1.1
  text "(.GBS)" at 313.745,180.922 h1.1
  text "Solder Resist" at 345.796,180.922 h1.1
M13 Component Bodies Top:
  text ".Layer_Name" at 14.453,-22.212 h1.52
M14 Component Bodies Bottom:
  text ".Layer_Name" at 14.453,-22.212 h1.52
M15 Courtyards Top:
  lines w0.152: 0.152,55.524 0.152,58.496 53.467,58.496 53.467,31.115 50.47,31.115 50.47,55.524 0.152,55.524
  text ".Layer_Name" at 14.453,-22.212 h1.52
M16 Courtyards Bottom:
  text ".Layer_Name" at 14.453,-22.212 h1.52
Drill Drawing:
  text ".legend" at 110.49,35.179 h1.52
  text "Drill Table" at 110.617,32.258 h1.52
  text "FOR PTH +/-3MILS" at 137.922,29.337 h1.52
  text "DRILL TOLERANCES:" at 110.744,29.083 h1.52
  text "FOR NPTH +/-2MILS" at 137.922,26.416 h1.52
  text ".Layer_Name" at 14.453,-22.212 h1.52

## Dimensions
100,100 to 100,0 on M2 Board Dimensions
0,100 to 100,100 on M2 Board Dimensions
